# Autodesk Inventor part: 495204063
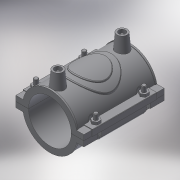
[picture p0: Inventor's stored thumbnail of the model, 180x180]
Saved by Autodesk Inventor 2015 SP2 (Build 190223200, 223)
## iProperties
Created: 2017-07
Part Number: 495204063
Material: Generic
Description: PLASSON REPAIR SADDLE 63
Document SubType Name: Modeling
Designer: KIM
Density: 1 g/cm^3
Appearance: Default
Author: KIM
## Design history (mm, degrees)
derived "495204.ipt"
feature "Solid1::495204.ipt"
tag "TaggingFeature1"
body "Solid1"
other parameters: "d0" = 63, "d1" = 78.75, "d3" = 15.75, "d4" = 118, "d5" = 0, "d6" = 0.1, "d8" = 0, "d19" = 6, "d20" = 6, "d21" = 70.8, "d23" = 0, "d24" = 35.4, "d26" = 0, "d27" = 3, "d28" = 3, "d29" = 3, "d30" = 21, "d31" = 6, "d32" = 0, "d33" = 0, "d34" = 0.6, "d40" = 40.95, "d41" = 64.9, "d43" = 0, "d45" = 0, "d47" = 42.525, "d48" = 47.2, "d50" = 0, "d70" = 15, "d72" = 0, "d73" = 6, "d75" = 5, "d76" = 0, "d77" = 3.15, "d78" = 60.5, "d79" = 15, "d80" = 47.2, "d82" = 5 deg, "d84" = 4, "d85" = 14, "d86" = 0, "d87" = 3, "d88" = 0, "d89" = 1, "d90" = 1, "d91" = 94.4, "d92" = 0, "d93" = 0.5, "d94" = 33.15789, "d96" = 80.325, "d97" = 2.36, "d98" = 0, "d99" = 47.2, "d100" = 0, "d102" = 1.18, "d_" = 63, "H_" = 29, "L_" = 118, "d_t" = 6
